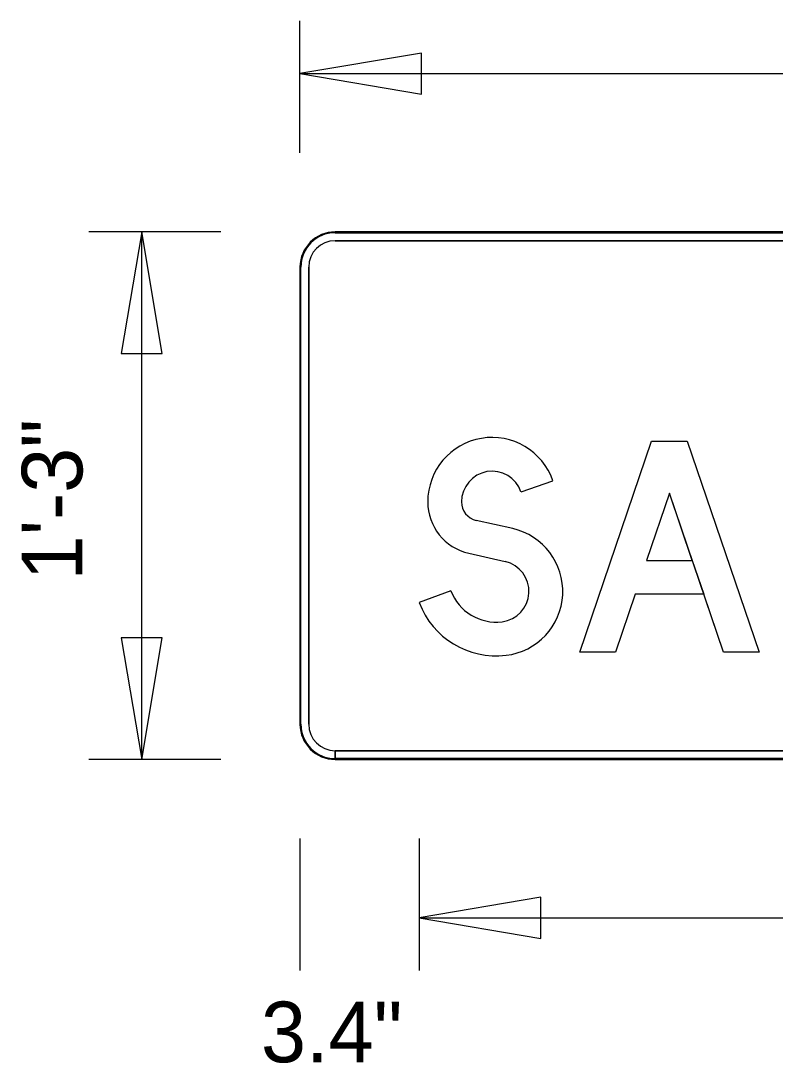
# Model space of a CAD drawing. Extents: x 0 to 770, y 0 to 495.
# Drawn here: x 201.9 to 245.4, y 409.1 to 469.3 of the extents above; entities that cross this region are included whole.
import ezdxf

# ---------------------------------------------------------------- set-up
doc = ezdxf.new("R2010")
doc.units = 0
for name, color, linetype in [('Dimension', 7, 'Continuous'), ('GSBWFill', 7, 'Continuous'), ('GSColorFill', 7, 'Continuous'), ('GSDims', 7, 'Continuous'), ('GSOutline', 7, 'Continuous'), ('TextStructures', 7, 'Continuous')]:
    doc.layers.add(name, color=color, linetype=linetype)

msp = doc.modelspace()

# ---------------------------------------------------------------- linework, layer by layer
at = {"layer": 'Dimension'}
for points in [[(218.022, 466.253), (225.039, 465.065), (225.039, 467.442)], [(208.886, 457.117), (207.697, 450.101), (210.074, 450.101)], [(208.886, 426.664), (210.074, 433.68), (207.697, 433.68)], [(224.904, 417.527), (231.921, 416.339), (231.921, 418.716)]]:
    msp.add_lwpolyline(points, close=True, dxfattribs=at)
at = {"layer": 'GSBWFill'}
for p, q in [((349.988, 457.117), (220.052, 457.117)), ((349.988, 457.117), (220.052, 457.117)), ((220.052, 456.61), (349.988, 456.61)), ((218.022, 455.087), (218.022, 428.694)), ((218.022, 455.087), (218.022, 428.694)), ((218.529, 428.694), (218.529, 455.087)), ((230.776, 442.114), (232.617, 442.753)), ((230.296, 439.988), (228.194, 440.466)), ((227.762, 438.566), (229.864, 438.088)), ((226.728, 436.406), (224.904, 435.719)), ((220.052, 426.664), (220.052, 427.171)), ((349.988, 427.171), (220.057, 427.171)), ((220.057, 427.171), (220.057, 426.664)), ((220.052, 426.664), (349.988, 426.664)), ((220.057, 426.664), (349.988, 426.664))]:
    msp.add_line(p, q, dxfattribs=at)
msp.add_lwpolyline([(234.162, 432.856), (238.304, 445.037), (240.375, 445.037), (244.517, 432.856), (242.458, 432.856), (239.339, 442.028), (238.022, 438.154), (240.656, 438.154), (241.319, 436.205), (237.36, 436.205), (236.221, 432.856)], close=True, dxfattribs=at)
for centre, radius, start, end in [((220.052, 455.087), 2.03, 90, 180), ((220.052, 455.087), 2.03, 90, 180), ((220.052, 455.087), 1.523, 90, 180), ((229.107, 441.535), 3.715, 19.13948, 180), ((229.107, 441.535), 1.766, 19.13948, 180), ((228.437, 441.535), 3.045, 180, 257.19149), ((228.437, 441.535), 1.096, 180, 257.19149), ((229.472, 436.365), 3.715, 276.78539, 77.19149), ((229.472, 436.365), 1.766, 276.78539, 77.19149), ((229.35, 437.393), 2.802, 200.64423, 276.78539), ((229.35, 437.393), 4.751, 200.64423, 276.78539), ((220.052, 428.694), 2.03, 180, 270), ((220.052, 428.694), 2.03, 180, 270), ((220.052, 428.694), 1.523, 180, 270)]:
    msp.add_arc(centre, radius, start, end, dxfattribs=at)
at = {"layer": 'GSColorFill'}
for p, q in [((349.988, 457.117), (220.052, 457.117)), ((349.988, 457.117), (220.052, 457.117)), ((349.988, 457.117), (220.052, 457.117)), ((220.052, 457.066), (349.988, 457.066)), ((220.052, 456.61), (349.988, 456.61)), ((218.022, 455.087), (218.022, 428.694)), ((218.022, 455.087), (218.022, 428.694)), ((218.022, 455.087), (218.022, 428.694)), ((218.073, 428.694), (218.073, 455.087)), ((218.529, 428.694), (218.529, 455.087)), ((230.776, 442.114), (232.617, 442.753)), ((230.296, 439.988), (228.194, 440.466)), ((227.762, 438.566), (229.864, 438.088)), ((226.728, 436.406), (224.904, 435.719)), ((220.052, 426.664), (220.052, 427.171)), ((349.988, 427.171), (220.057, 427.171)), ((220.057, 427.171), (220.057, 426.664)), ((220.052, 426.664), (220.052, 426.714)), ((220.052, 426.664), (349.988, 426.664)), ((349.988, 426.714), (220.053, 426.714)), ((220.053, 426.714), (220.053, 426.664)), ((220.053, 426.664), (349.988, 426.664)), ((220.057, 426.664), (349.988, 426.664))]:
    msp.add_line(p, q, dxfattribs=at)
msp.add_lwpolyline([(234.162, 432.856), (238.304, 445.037), (240.375, 445.037), (244.517, 432.856), (242.458, 432.856), (239.339, 442.028), (238.022, 438.154), (240.656, 438.154), (241.319, 436.205), (237.36, 436.205), (236.221, 432.856)], close=True, dxfattribs=at)
for centre, radius, start, end in [((220.052, 455.087), 2.03, 90, 180), ((220.052, 455.087), 2.03, 90, 180), ((220.052, 455.087), 2.03, 90, 180), ((220.052, 455.087), 1.979, 90, 180), ((220.052, 455.087), 1.523, 90, 180), ((229.107, 441.535), 3.715, 19.13948, 180), ((229.107, 441.535), 1.766, 19.13948, 180), ((228.437, 441.535), 3.045, 180, 257.19149), ((228.437, 441.535), 1.096, 180, 257.19149), ((229.472, 436.365), 3.715, 276.78539, 77.19149), ((229.472, 436.365), 1.766, 276.78539, 77.19149), ((229.35, 437.393), 2.802, 200.64423, 276.78539), ((229.35, 437.393), 4.751, 200.64423, 276.78539), ((220.052, 428.694), 2.03, 180, 270), ((220.052, 428.694), 2.03, 180, 270), ((220.052, 428.694), 2.03, 180, 270), ((220.052, 428.694), 1.979, 180, 270), ((220.052, 428.694), 1.523, 180, 270)]:
    msp.add_arc(centre, radius, start, end, dxfattribs=at)
at = {"layer": 'GSDims'}
for p, q in [((218.022, 461.685), (218.022, 469.299)), ((218.022, 466.253), (352.018, 466.253)), ((213.454, 457.117), (205.84, 457.117)), ((208.886, 426.664), (208.886, 457.117)), ((213.454, 426.664), (205.84, 426.664)), ((218.022, 422.095), (218.022, 414.482)), ((224.904, 422.095), (224.904, 414.482)), ((224.904, 422.095), (224.904, 414.482)), ((224.904, 417.527), (345.136, 417.527))]:
    msp.add_line(p, q, dxfattribs=at)
at = {"layer": 'GSOutline'}
for p, q in [((349.988, 457.117), (220.052, 457.117)), ((349.988, 457.117), (220.052, 457.117)), ((349.988, 456.61), (220.052, 456.61)), ((218.022, 455.087), (218.022, 428.694)), ((218.022, 455.087), (218.022, 428.694)), ((218.529, 455.087), (218.529, 428.694)), ((230.776, 442.114), (232.617, 442.753)), ((230.296, 439.988), (228.194, 440.466)), ((227.762, 438.566), (229.864, 438.088)), ((226.728, 436.406), (224.904, 435.719)), ((220.052, 427.171), (349.988, 427.171)), ((220.052, 426.664), (349.988, 426.664)), ((220.052, 426.664), (349.988, 426.664))]:
    msp.add_line(p, q, dxfattribs=at)
for points in [[(237.36, 436.205), (236.221, 432.856), (234.162, 432.856), (238.304, 445.037), (240.375, 445.037), (244.517, 432.856), (242.458, 432.856), (241.319, 436.205)], [(238.022, 438.154), (240.657, 438.154), (239.339, 442.028)]]:
    msp.add_lwpolyline(points, close=True, dxfattribs=at)
for centre, radius, start, end in [((220.052, 455.087), 2.03, 90, 180), ((220.052, 455.087), 2.03, 90, 180), ((220.052, 455.087), 1.523, 90, 180), ((229.107, 441.535), 3.715, 19.13948, 180), ((229.107, 441.535), 1.766, 19.13948, 180), ((228.437, 441.535), 3.045, 180, 257.19149), ((228.437, 441.535), 1.096, 180, 257.19149), ((229.472, 436.365), 3.715, 276.78539, 77.19149), ((229.472, 436.365), 1.766, 276.78539, 77.19149), ((229.35, 437.393), 2.802, 200.64423, 276.78539), ((229.35, 437.393), 4.751, 200.64423, 276.78539), ((220.052, 428.694), 2.03, 180, 270), ((220.052, 428.694), 2.03, 180, 270), ((220.052, 428.694), 1.523, 180, 270)]:
    msp.add_arc(centre, radius, start, end, dxfattribs=at)

# ---------------------------------------------------------------- texts
at = {"layer": 'TextStructures'}
msp.add_text('1\'-3"', height=3.5, rotation=90, dxfattribs=at).set_placement((205.464, 436.999))
msp.add_text('3.4"', height=3.5, dxfattribs=at).set_placement((215.769, 409.184))

doc.saveas('drawing.dxf')
